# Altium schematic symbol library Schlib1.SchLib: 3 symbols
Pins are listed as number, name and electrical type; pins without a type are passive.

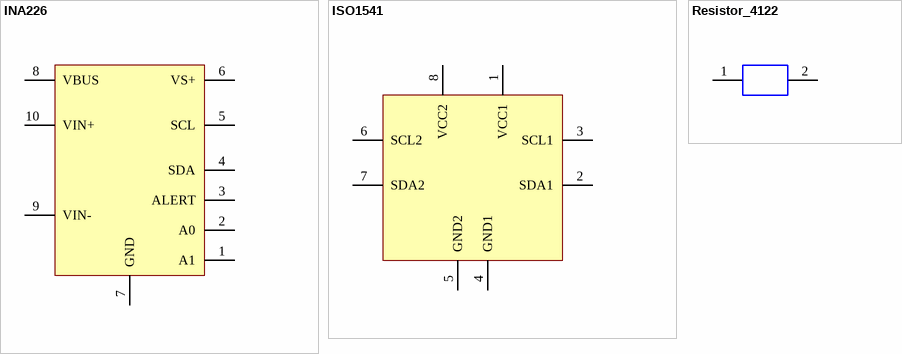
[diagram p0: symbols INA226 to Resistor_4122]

## INA226
designator U?
Manufacturer: Used in BOM report; SymbolVersion: use current date i.e. 2008-05-20; SymbolCreator: Use a-id; CompType: Used in some BOM reports.  Useful for finding later.; U/M: EA, IN, or GM
footprint DGS0010A_M (TSSOP, 10-Leads, Body 3x3mm, Pitch 0.5mm, IPC Low Density)
pins: 1 A1, 2 A0, 3 ALERT, 4 SDA, 5 SCL, 6 VS+, 7 GND, 8 VBUS, 9 VIN-, 10 VIN+

## ISO1541
designator U?
Manufacturer: Used in BOM report; SymbolVersion: use current date i.e. 2008-05-20; SymbolCreator: Use a-id; CompType: Used in some BOM reports.  Useful for finding later.; U/M: EA, IN, or GM
footprint D0008A_N (SOIC, 8-Leads, Body 4.9x3.9mm, Pitch 1.27mm, IPC Medium Density)
pins: 1 VCC1, 2 SDA1, 3 SCL1, 4 GND1, 5 GND2, 6 SCL2, 7 SDA2, 8 VCC2

## Resistor_4122
designator R?, comment Used in BOM report
SymbolVersion: use current date i.e. 2008-05-20; SymbolCreator: Use a-id; CompType: Used in some BOM reports.  Useful for finding later.; U/M: EA, IN, or GM
footprint Resistor_4122
pins: 1, 2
